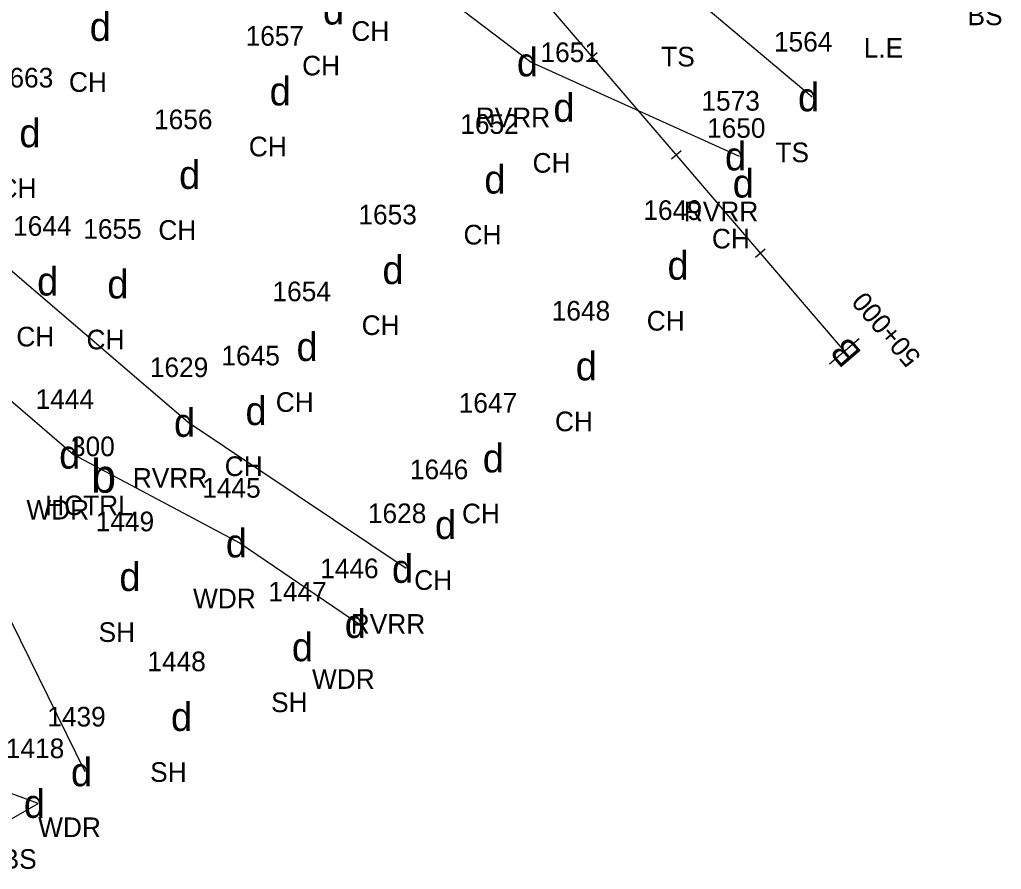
# Model space of a CAD drawing. Extents: x 461160 to 461373, y 202903 to 203086.
# Drawn here: x 461314.15 to 461352.13, y 202928.7 to 202961.57 of the extents above; entities that cross this region are included whole.
import ezdxf

# ---------------------------------------------------------------- set-up
doc = ezdxf.new("R2010")
doc.units = 0
for name, color, linetype in [('Level 1', 7, 'Continuous'), ('Level 12', 7, 'Continuous'), ('Level 13', 7, 'Continuous'), ('Level 14', 7, 'Continuous'), ('Level 17', 7, 'Continuous'), ('Level 46', 7, 'Continuous'), ('Level 47', 7, 'Continuous'), ('Level 48', 7, 'Continuous'), ('Level 49', 7, 'Continuous')]:
    doc.layers.add(name, color=color, linetype=linetype)

msp = doc.modelspace()

# ---------------------------------------------------------------- linework, layer by layer
at = {"layer": 'Level 12'}
msp.add_line((461346.056, 202948.738), (461294.056, 203009.532), dxfattribs=at)
at = {"layer": 'Level 13'}
for points in [[(461336.116, 202959.974), (461336.496, 202960.299)], [(461339.366, 202956.175), (461339.746, 202956.5)], [(461342.616, 202952.375), (461342.996, 202952.7)], [(461345.486, 202948.25), (461346.626, 202949.226)]]:
    msp.add_lwpolyline(points, dxfattribs=at)
at = {"layer": 'Level 14'}
msp.add_lwpolyline([(461316.688, 202932.462), (461313.104, 202939.736), (461307.447, 202948.079), (461304.23, 202954.345), (461309.796, 202950.292), (461316.233, 202944.748), (461322.68, 202941.312), (461327.281, 202938.198)], dxfattribs=at)
at = {"layer": 'Level 17'}
for points in [[(461329.105, 202940.329), (461320.674, 202945.977), (461310.964, 202954.304), (461302.434, 202959.989), (461295.777, 202967.953), (461287.62, 202974.31), (461283.863, 202976.623)], [(461319.309, 202973.643), (461323.731, 202969.886), (461328.385, 202964.15), (461333.938, 202959.923), (461341.989, 202956.284)]]:
    msp.add_lwpolyline(points, dxfattribs=at)
at = {"layer": 'Level 48'}
for points in [[(461344.812, 202958.571), (461340.392, 202962.274), (461334.167, 202966.108), (461327.392, 202969.428), (461321.29, 202974.86)], [(461344.812, 202958.571), (461340.392, 202962.274), (461334.167, 202966.108), (461327.392, 202969.428), (461321.29, 202974.86)], [(461294.593, 202952.063), (461290.48, 202949.284), (461287.747, 202948.275), (461286.711, 202947.403), (461288.313, 202945.529), (461294.278, 202942.049), (461301.603, 202936.541), (461306.215, 202932.756), (461310.378, 202928.695), (461312.884, 202930.112), (461314.866, 202931.237), (461309.977, 202933.052), (461306.465, 202937.375), (461306.039, 202938.806)]]:
    msp.add_lwpolyline(points, dxfattribs=at)

# ---------------------------------------------------------------- texts
at = {"layer": 'Level 1'}
msp.add_text('b', height=1.3, dxfattribs=at).set_placement((461316.918, 202943.266))
at = {"layer": 'Level 12'}
msp.add_text('B', height=1, rotation=130.5419, dxfattribs=at).set_placement((461346.761, 202948.683))
at = {"layer": 'Level 13'}
msp.add_text('50+000', height=0.75, rotation=130.5419, dxfattribs=at).set_placement((461349.056, 202948.538))
at = {"layer": 'Level 46'}
for s, p in [(' BS  ', (461350.539, 202961.351)), (' CH  ', (461326.704, 202960.744)), (' L.E  ', (461346.523, 202960.095)), (' TS  ', (461338.69, 202959.754)), (' CH  ', (461324.8, 202959.407)), (' CH  ', (461315.779, 202958.772)), (' RVRR  ', (461331.515, 202957.403)), (' CH  ', (461322.738, 202956.277)), (' TS  ', (461343.11, 202956.051)), (' CH  ', (461333.715, 202955.643)), (' CH  ', (461313.056, 202954.66)), (' RVRR  ', (461339.566, 202953.764)), (' CH  ', (461319.237, 202953.047)), (' CH  ', (461331.043, 202952.867)), (' CH  ', (461340.652, 202952.713)), (' CH  ', (461338.129, 202949.536)), (' CH  ', (461327.103, 202949.365)), (' CH  ', (461313.745, 202948.923)), (' CH  ', (461316.458, 202948.81)), (' CH  ', (461323.779, 202946.392)), (' CH  ', (461334.581, 202945.643)), (' CH  ', (461321.805, 202943.91)), (' RVRR  ', (461318.251, 202943.457)), (' WDR  ', (461314.133, 202942.228)), (' HCTRL  ', (461314.861, 202942.396)), (' CH  ', (461330.983, 202942.081)), (' CH  ', (461329.133, 202939.506)), (' WDR  ', (461320.58, 202938.792)), (' RVRR  ', (461326.682, 202937.809)), (' SH  ', (461316.926, 202937.493)), (' WDR  ', (461325.181, 202935.678)), (' SH  ', (461323.599, 202934.777)), (' SH  ', (461318.921, 202932.079)), (' WDR  ', (461314.588, 202929.942)), (' BS  ', (461313.176, 202928.717))]:
    msp.add_text(s, height=0.76, dxfattribs=at).set_placement(p)
at = {"layer": 'Level 47'}
for p in [(461325.886, 202961.377), (461316.865, 202960.742), (461333.388, 202959.373), (461323.824, 202958.247), (461344.262, 202958.021), (461334.801, 202957.613), (461314.142, 202956.63), (461341.439, 202955.734), (461320.323, 202955.017), (461332.129, 202954.837), (461341.738, 202954.683), (461328.189, 202951.335), (461339.215, 202951.506), (461314.831, 202950.893), (461317.544, 202950.78), (461324.865, 202948.362), (461335.667, 202947.613), (461322.891, 202945.88), (461320.124, 202945.427), (461315.683, 202944.198), (461332.069, 202944.051), (461330.219, 202941.476), (461322.13, 202940.762), (461328.555, 202939.779), (461318.012, 202939.463), (461326.731, 202937.648), (461324.685, 202936.747), (461320.007, 202934.049), (461316.138, 202931.912), (461314.316, 202930.687)]:
    msp.add_text('d', height=1.1, dxfattribs=at).set_placement(p)
at = {"layer": 'Level 49'}
for s, p in [(' 1657 ', (461322.612, 202960.557)), (' 1564 ', (461343.05, 202960.331)), (' 1651 ', (461334.02, 202959.923)), (' 1663 ', (461312.912, 202958.94)), (' 1573 ', (461340.245, 202958.044)), (' 1656 ', (461319.072, 202957.327)), (' 1652 ', (461330.917, 202957.147)), (' 1650 ', (461340.463, 202956.993)), (' 1653 ', (461326.977, 202953.645)), (' 1649 ', (461338, 202953.816)), (' 1644 ', (461313.619, 202953.203)), (' 1655 ', (461316.332, 202953.09)), (' 1654 ', (461323.653, 202950.672)), (' 1648 ', (461334.455, 202949.923)), (' 1645 ', (461321.679, 202948.19)), (' 1629 ', (461318.909, 202947.737)), (' 1444 ', (461314.489, 202946.508)), (' 1647 ', (461330.857, 202946.361)), (' 300 ', (461315.857, 202944.676)), (' 1646 ', (461328.968, 202943.786)), (' 1445 ', (461320.936, 202943.072)), (' 1628 ', (461327.343, 202942.089)), (' 1449 ', (461316.815, 202941.773)), (' 1446 ', (461325.498, 202939.958)), (' 1447 ', (461323.491, 202939.057)), (' 1448 ', (461318.813, 202936.359)), (' 1439 ', (461314.941, 202934.222)), (' 1418 ', (461313.338, 202932.997))]:
    msp.add_text(s, height=0.76, dxfattribs=at).set_placement(p)

doc.saveas('drawing.dxf')
